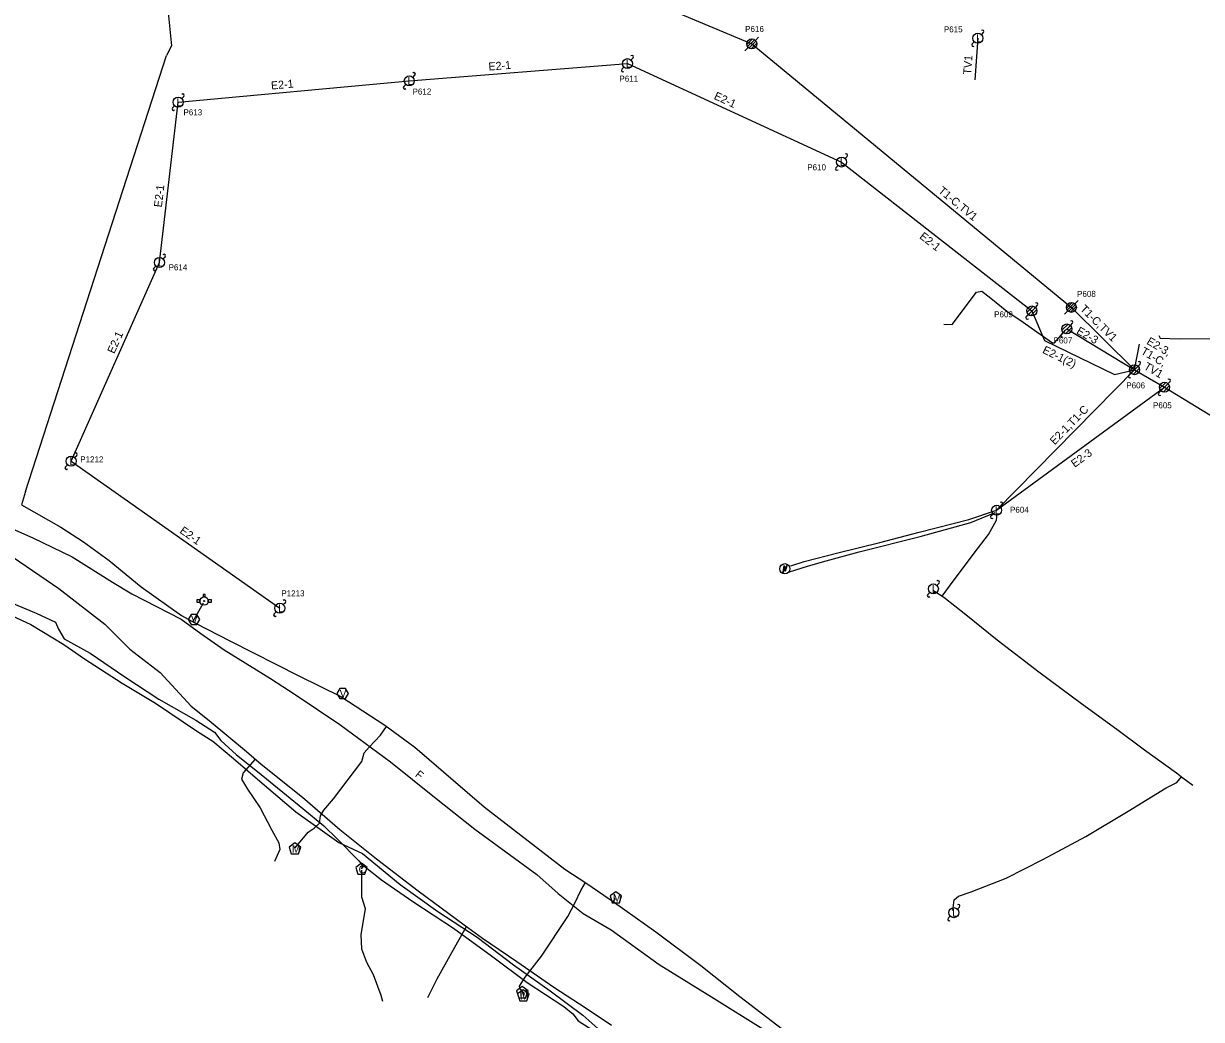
# Model space of a CAD drawing. Extents: x 1614474 to 1865144, y 1098877 to 1212550.
# Drawn here: x 1811697 to 1812286, y 1189385 to 1189883 of the extents above; entities that cross this region are included whole.
import ezdxf

# ---------------------------------------------------------------- set-up
doc = ezdxf.new("R2010")
doc.units = 0
for name, color, linetype in [('RD_EX_SU_Elec', 7, 'Continuous'), ('RD_EX_SU_Gas', 7, 'Continuous'), ('RD_EX_SU_H2O', 7, 'Continuous'), ('RD_EX_SU_Ovhd', 7, 'Continuous'), ('RD_EX_SU_Pole', 7, 'Continuous'), ('RD_EX_SU_Telecom', 7, 'Continuous'), ('RD_EX_SU_TX_Pole', 7, 'Continuous'), ('RD_EX_SU_TX_Telecom', 7, 'Continuous')]:
    doc.layers.add(name, color=color, linetype=linetype)

# ---------------------------------------------------------------- blocks, each defined once
blk = doc.blocks.new('SUE_PTP')
at = {"layer": 'RD_EX_SU_Pole'}
for p, q in [((-2.48, -0.33), (0.33, 2.48)), ((-2.1, -1.36), (1.36, 2.1)), ((-1.4, -2.08), (2.08, 1.4)), ((-0.38, -2.47), (2.47, 0.38)), ((1.77, 1.77), (3.42, 3.42)), ((-3.42, -3.42), (-1.77, -1.77)), ((1.52, -1.99), (1.99, -1.52))]:
    blk.add_line(p, q, dxfattribs=at)
blk.add_circle((0, 0), 2.5, dxfattribs=at)
blk = doc.blocks.new('SUE_PP')
at = {"layer": 'RD_EX_SU_Pole'}
for p, q in [((-2.41, -0.65), (0.65, 2.41)), ((-1.77, -1.77), (1.77, 1.77)), ((-0.65, -2.41), (2.41, 0.65)), ((1.77, 1.77), (2.83, 2.83)), ((-2.83, -2.83), (-1.77, -1.77))]:
    blk.add_line(p, q, dxfattribs=at)
blk.add_circle((0, 0), 2.5, dxfattribs=at)
for centre, start, end in [((2.3, 3.36), 315, 135), ((-2.3, -3.36), 135, 315)]:
    blk.add_arc(centre, 0.75, start, end, dxfattribs=at)
blk = doc.blocks.new('SUE_ETM')
at = {"layer": 'RD_EX_SU_Elec'}
blk.add_lwpolyline([(1.24, 2.04), (0.23, -1.41), (-0.27, 0.46), (-1.03, -2.36), (-0.34, 1.55), (0.22, -0.39)], close=True, dxfattribs=at)
blk.add_circle((0, 0), 2.55, dxfattribs=at)
blk = doc.blocks.new('SUE_TVP')
at = {"layer": 'RD_EX_SU_Telecom'}
blk.add_lwpolyline([(0, 3), (-2.85, 0.93), (-1.76, -2.43), (1.76, -2.43), (2.85, 0.93)], close=True, dxfattribs=at)
blk.add_text('C', height=4, dxfattribs=at).set_placement((-1.43, -2))
blk = doc.blocks.new('SUE_WM')
at = {"layer": 'RD_EX_SU_H2O'}
blk.add_lwpolyline([(0, 3.05), (-2.9, 0.94), (-1.79, -2.47), (1.79, -2.47), (2.9, 0.94)], close=True, dxfattribs=at)
blk.add_text('M', height=3.75, dxfattribs=at).set_placement((-1.43, -1.88))
blk = doc.blocks.new('SUE_WV')
at = {"layer": 'RD_EX_SU_H2O'}
blk.add_lwpolyline([(2.89, 0), (1.44, 2.5), (-1.44, 2.5), (-2.89, 0), (-1.44, -2.5), (1.44, -2.5)], close=True, dxfattribs=at)
blk.add_text('V', height=3.75, dxfattribs=at).set_placement((-1.43, -1.88))
blk = doc.blocks.new('SUE_WFH')
at = {"layer": 'RD_EX_SU_H2O'}
for p, q in [((-2.01, 0.6), (-3.65, 0.6)), ((-3.65, 0.6), (-3.65, -0.45)), ((-0.48, 3.38), (-0.48, 2.04)), ((0.57, 3.38), (-0.48, 3.38)), ((0.57, 2.02), (0.57, 3.38)), ((3.7, 0.6), (2.01, 0.6)), ((3.7, -0.45), (3.7, 0.6)), ((-3.65, -0.45), (-2.05, -0.45)), ((2.05, -0.45), (3.7, -0.45))]:
    blk.add_line(p, q, dxfattribs=at)
for radius in [2.1, 0.263]:
    blk.add_circle((0, 0), radius, dxfattribs=at)
for start, end in [(163.3387, 192.31502), (74.24552, 103.21276), (347.68498, 16.6613)]:
    blk.add_arc((0, 0), 2.1, start, end, dxfattribs=at)

msp = doc.modelspace()

# ---------------------------------------------------------------- linework, layer by layer
at = {"layer": 'RD_EX_SU_Elec'}
for points in [[(1812264.91, 1189727.31), (1812265.67, 1189726.04), (1812275.26, 1189725.72), (1812293.9, 1189725.79), (1812324.91, 1189726.47), (1812339.96, 1189726.45), (1812342, 1189727.19), (1812342.85, 1189729.51), (1812344.8, 1189746.63), (1812345.47, 1189768.56), (1812345.08, 1189790.52), (1812345.62, 1189813.9), (1812348.11, 1189828.63), (1812352.6, 1189838.52), (1812358.64, 1189853.73), (1812362.26, 1189854.61), (1812373.02, 1189852.36), (1812375.77, 1189853.01), (1812378.77, 1189855.94), (1812381.54, 1189860.45), (1812381.16, 1189864.31), (1812374.37, 1189871.78), (1812363.55, 1189880.36), (1812360.11, 1189887.91)], [(1812157.46, 1189732.89), (1812161.71, 1189732.8), (1812173.83, 1189748.94), (1812176.52, 1189749.55), (1812181.03, 1189746), (1812188.99, 1189739.47), (1812197.08, 1189733.89), (1812203.94, 1189729.08), (1812211.78, 1189723.64), (1812212.83, 1189723.64), (1812218.36, 1189729.98)], [(1812080.38, 1189609.13), (1812089.32, 1189611.99), (1812096.75, 1189614.2), (1812115.15, 1189619.16), (1812145.63, 1189626.78), (1812171.01, 1189633.82), (1812183.13, 1189638.8)], [(1812156.64, 1189596.96), (1812160.33, 1189602.07), (1812172.65, 1189618.48), (1812179.9, 1189627.9), (1812183.89, 1189634.91), (1812184.18, 1189638.37)], [(1812152.4, 1189599.89), (1812157.43, 1189596.42), (1812168.45, 1189587.78), (1812184.22, 1189575.11), (1812205.04, 1189559.15), (1812226.24, 1189543.39), (1812243.94, 1189530.5), (1812257.79, 1189520.12), (1812273.87, 1189508.71), (1812276.99, 1189506.25), (1812281.97, 1189502.57)], [(1812161.96, 1189439.78), (1812162.64, 1189445.19), (1812164.74, 1189447.02), (1812171.15, 1189449.17), (1812188.59, 1189456), (1812206.94, 1189465.3), (1812228.46, 1189476.83), (1812249.64, 1189489.48), (1812268.67, 1189501.17), (1812273.98, 1189503.93), (1812276.4, 1189506.71)]]:
    msp.add_lwpolyline(points, dxfattribs=at)
at = {"layer": 'RD_EX_SU_Gas'}
for points in [[(1811692.31, 1189616.25), (1811715.05, 1189600.87), (1811738.04, 1189583.07), (1811750.54, 1189570.51), (1811765.6, 1189558.89), (1811781.13, 1189542.05), (1811790.18, 1189534.92), (1811808.75, 1189519.41), (1811816.19, 1189513.02), (1811836.76, 1189496.52), (1811855.49, 1189480.41), (1811873.84, 1189465.7), (1811894.68, 1189449.62), (1811917.72, 1189432.69), (1811926.85, 1189425.98), (1811944.01, 1189414.44), (1811962.44, 1189401.55), (1811978.62, 1189391.11), (1811991.38, 1189382.56)], [(1811813.24, 1189515.56), (1811807.12, 1189508.75), (1811806.25, 1189505.55), (1811809.31, 1189500.44), (1811815.62, 1189491.11), (1811821.48, 1189479.96), (1811824.98, 1189473.64), (1811825.52, 1189470.37), (1811822.86, 1189464.34)], [(1811899.52, 1189396.32), (1811904.22, 1189405.75), (1811911.47, 1189418.83), (1811918.85, 1189431.86)]]:
    msp.add_lwpolyline(points, dxfattribs=at)
at = {"layer": 'RD_EX_SU_H2O'}
for p, q in [((1811698.38, 1189649.37), (1811768.81, 1189867.23)), ((1811781.92, 1189584.24), (1811787.36, 1189593.71)), ((1811992.21, 1189444.25), (1811993.36, 1189445.94))]:
    msp.add_line(p, q, dxfattribs=at)
for points in [[(1811749.01, 1190098.07), (1811749.34, 1190093.41), (1811749.33, 1190089.26), (1811749.37, 1190061.81), (1811749.88, 1190048.07), (1811750.21, 1190035.15), (1811751.18, 1190011.76), (1811751.52, 1190001.48), (1811754.59, 1189978.56), (1811759.5, 1189949.27), (1811762.38, 1189936.11), (1811766.27, 1189918.58), (1811768.53, 1189900.63), (1811771.29, 1189872.1), (1811768.81, 1189867.23)], [(1811698.38, 1189649.37), (1811696.33, 1189642.69), (1811716.07, 1189631.57), (1811727.27, 1189624.19), (1811740.19, 1189614.8), (1811756.23, 1189601.68), (1811776.38, 1189587.41), (1811783.03, 1189583.6), (1811800.81, 1189574.54), (1811834.94, 1189557.09), (1811855.92, 1189546.76), (1811878.04, 1189532.45), (1811892.99, 1189521.5), (1811927.74, 1189491.64), (1811968.06, 1189460.58), (1811978.97, 1189453.42), (1811992.89, 1189443.78), (1812013.48, 1189429.12), (1812036.07, 1189412.42), (1812055.57, 1189396.84), (1812100.91, 1189362.09), (1812129.54, 1189341.4), (1812152.59, 1189324.09), (1812186.12, 1189296.74)], [(1811833.17, 1189471.16), (1811839.64, 1189479.07), (1811842.69, 1189480.95), (1811845.36, 1189483.48), (1811845.85, 1189487.16), (1811847.57, 1189490.08), (1811852.4, 1189495.67), (1811866.54, 1189514.32), (1811867.72, 1189518.7), (1811870.1, 1189521.47), (1811875.88, 1189527.52), (1811878.77, 1189531.91)], [(1811947.49, 1189397.66), (1811947.36, 1189398.85), (1811945.67, 1189400.6), (1811945.28, 1189402.05), (1811948.11, 1189406.49), (1811956.4, 1189417.11), (1811969.45, 1189436.94), (1811973.24, 1189443.82), (1811975.95, 1189449.81), (1811978.25, 1189453.9)]]:
    msp.add_lwpolyline(points, dxfattribs=at)
at = {"layer": 'RD_EX_SU_Ovhd'}
for p, q in [((1811952.33, 1189919.06), (1812061.47, 1189873.07)), ((1812174.5, 1189875.89), (1812172.94, 1189855.19)), ((1812061.47, 1189873.07), (1812221.25, 1189741.38)), ((1811890.24, 1189854.59), (1811999.3, 1189863.2)), ((1811999.3, 1189863.2), (1812106.35, 1189814.02)), ((1811774.66, 1189843.94), (1811890.24, 1189854.59)), ((1811765.29, 1189763.8), (1811774.66, 1189843.94)), ((1812106.35, 1189814.02), (1812201.52, 1189739.58)), ((1811721.11, 1189664.49), (1811765.29, 1189763.8)), ((1812221.25, 1189741.38), (1812252.81, 1189710.2)), ((1812218.97, 1189730.56), (1812252.81, 1189710.2)), ((1812252.81, 1189710.2), (1812255.27, 1189723.05)), ((1812183.9, 1189639.95), (1812252.81, 1189710.2)), ((1812252.81, 1189710.2), (1812267.77, 1189701.43)), ((1812183.9, 1189639.95), (1812267.77, 1189701.43)), ((1812267.77, 1189701.43), (1812440.67, 1189595.6)), ((1811721.11, 1189664.49), (1811825.45, 1189590.98))]:
    msp.add_line(p, q, dxfattribs=at)
msp.add_lwpolyline([(1812201.52, 1189739.58), (1812207.78, 1189724.76), (1812242.82, 1189707.8), (1812252.81, 1189710.2)], dxfattribs=at)
at = {"layer": 'RD_EX_SU_Pole'}
for p, q in [((1812171.67, 1189873.06), (1812172.73, 1189874.12)), ((1812176.26, 1189877.66), (1812177.32, 1189878.72)), ((1812001.07, 1189864.96), (1812002.13, 1189866.03)), ((1811892.01, 1189856.36), (1811893.07, 1189857.42)), ((1811996.47, 1189860.37), (1811997.53, 1189861.43)), ((1811887.41, 1189851.77), (1811888.47, 1189852.83)), ((1811776.43, 1189845.7), (1811777.49, 1189846.76)), ((1811771.84, 1189841.11), (1811772.9, 1189842.17)), ((1812108.12, 1189815.79), (1812109.18, 1189816.85)), ((1812103.52, 1189811.19), (1812104.58, 1189812.25)), ((1811762.46, 1189760.97), (1811763.52, 1189762.03)), ((1811767.06, 1189765.57), (1811768.12, 1189766.63)), ((1812223.02, 1189743.15), (1812224.67, 1189744.8)), ((1812199.11, 1189738.93), (1812202.17, 1189741.99)), ((1812199.75, 1189737.81), (1812203.29, 1189741.34)), ((1812200.88, 1189737.16), (1812203.94, 1189740.22)), ((1812203.29, 1189741.34), (1812204.35, 1189742.41)), ((1812217.82, 1189737.96), (1812219.48, 1189739.61)), ((1812218.77, 1189741.05), (1812221.58, 1189743.86)), ((1812219.15, 1189740.02), (1812222.61, 1189743.48)), ((1812219.85, 1189739.3), (1812223.32, 1189742.78)), ((1812220.87, 1189738.91), (1812223.72, 1189741.76)), ((1812222.77, 1189739.39), (1812223.23, 1189739.86)), ((1812198.69, 1189736.75), (1812199.75, 1189737.81)), ((1812250.39, 1189709.55), (1812253.46, 1189712.61)), ((1812251.04, 1189708.43), (1812254.58, 1189711.97)), ((1812252.16, 1189707.79), (1812255.22, 1189710.85)), ((1812254.58, 1189711.97), (1812255.64, 1189713.03)), ((1812249.98, 1189707.37), (1812251.04, 1189708.43)), ((1812265.36, 1189700.78), (1812268.42, 1189703.84)), ((1812266, 1189699.66), (1812269.54, 1189703.19)), ((1812269.54, 1189703.19), (1812270.6, 1189704.25)), ((1812264.94, 1189698.6), (1812266, 1189699.66)), ((1812267.13, 1189699.01), (1812270.19, 1189702.07)), ((1811718.28, 1189661.66), (1811719.34, 1189662.72)), ((1811722.87, 1189666.26), (1811723.94, 1189667.32)), ((1812181.07, 1189637.12), (1812182.13, 1189638.18)), ((1812185.66, 1189641.71), (1812186.72, 1189642.78)), ((1812154.03, 1189602.41), (1812155.09, 1189603.47)), ((1812149.44, 1189597.82), (1812150.5, 1189598.88)), ((1811827.21, 1189592.75), (1811828.27, 1189593.81)), ((1811822.62, 1189588.16), (1811823.68, 1189589.22)), ((1812164.26, 1189440.55), (1812165.32, 1189441.61)), ((1812159.66, 1189435.95), (1812160.72, 1189437.01))]:
    msp.add_line(p, q, dxfattribs=at)
for centre in [(1812174.5, 1189875.89), (1811999.3, 1189863.2), (1811890.24, 1189854.59), (1811774.66, 1189843.94), (1812106.35, 1189814.02), (1811765.29, 1189763.8), (1812201.52, 1189739.58), (1812221.25, 1189741.38), (1812252.81, 1189710.2), (1812267.77, 1189701.43), (1811721.11, 1189664.49), (1812183.9, 1189639.95), (1812152.26, 1189600.64), (1811825.45, 1189590.98), (1812162.49, 1189438.78)]:
    msp.add_circle(centre, 2.5, dxfattribs=at)
for centre, start, end in [((1812176.79, 1189879.25), 315, 135), ((1812172.2, 1189872.53), 135, 315), ((1812001.6, 1189866.56), 315, 135), ((1811892.54, 1189857.95), 315, 135), ((1811997, 1189859.84), 135, 315), ((1811887.94, 1189851.24), 135, 315), ((1811776.96, 1189847.3), 315, 135), ((1811772.37, 1189840.58), 135, 315), ((1812108.65, 1189817.38), 315, 135), ((1812104.05, 1189810.66), 135, 315), ((1811767.59, 1189767.16), 315, 135), ((1811762.99, 1189760.44), 135, 315), ((1812203.82, 1189742.94), 315, 135), ((1812199.22, 1189736.22), 135, 315), ((1812255.11, 1189713.56), 315, 135), ((1812250.51, 1189706.84), 135, 315), ((1812270.07, 1189704.78), 315, 135), ((1812265.47, 1189698.07), 135, 315), ((1811723.41, 1189667.85), 315, 135), ((1811718.81, 1189661.13), 135, 315), ((1812186.19, 1189643.31), 315, 135), ((1812181.6, 1189636.59), 135, 315), ((1812154.56, 1189604), 315, 135), ((1812149.97, 1189597.29), 135, 315), ((1811827.74, 1189594.34), 315, 135), ((1811823.15, 1189587.63), 135, 315), ((1812164.79, 1189442.14), 315, 135), ((1812160.19, 1189435.42), 135, 315)]:
    msp.add_arc(centre, 0.75, start, end, dxfattribs=at)
at = {"layer": 'RD_EX_SU_Telecom'}
for points in [[(1812080.94, 1189612.23), (1812087.64, 1189614.38), (1812104.55, 1189618.61), (1812125.45, 1189623.75), (1812145.2, 1189628.92), (1812170.06, 1189635.3), (1812183.37, 1189639.83)], [(1811678.57, 1189636.54), (1811702.02, 1189626.09), (1811721.66, 1189616.6), (1811741.84, 1189603.98), (1811751.48, 1189598.22), (1811776.15, 1189585.54), (1811786, 1189578.31), (1811797.6, 1189570.11), (1811820.85, 1189555.77), (1811833.2, 1189547.84), (1811855.44, 1189532.83), (1811880.8, 1189514.22), (1811902.8, 1189496.6), (1811923.07, 1189480.55), (1811953.95, 1189457.83), (1811964.7, 1189448.3), (1811977.24, 1189438.31), (1811991.12, 1189430.27), (1812015.08, 1189412.93), (1812041.31, 1189396.63), (1812067.45, 1189380.42)], [(1811576.48, 1189627.18), (1811591.3, 1189624), (1811619.72, 1189617.72), (1811647.4, 1189609.75), (1811676.84, 1189599.71), (1811703.64, 1189588.56), (1811713.39, 1189584.03), (1811714.86, 1189580.51), (1811717.73, 1189575.64), (1811730.58, 1189568.58), (1811747.95, 1189556.7), (1811765.04, 1189545.45), (1811783.53, 1189535.07), (1811792.79, 1189528.95), (1811796.05, 1189524.9), (1811803.9, 1189517.67), (1811814.32, 1189509.32), (1811837.05, 1189490.91), (1811847.41, 1189482.26), (1811854.37, 1189475.52), (1811865.03, 1189464.68), (1811866.6, 1189462.7), (1811866.26, 1189460.76)], [(1811674.94, 1189594.9), (1811701.01, 1189582.82), (1811717.47, 1189572.89), (1811727.78, 1189565.75), (1811746.64, 1189553.45), (1811763.29, 1189543.56), (1811784.27, 1189529.35), (1811792, 1189524.45), (1811802.3, 1189515.8), (1811815.51, 1189504.47), (1811833.48, 1189489.14), (1811846.85, 1189479.64), (1811855.03, 1189473.8), (1811866.89, 1189468.42), (1811885.7, 1189452.8), (1811904.46, 1189439.39), (1811924.08, 1189426.58), (1811942.4, 1189412.71), (1811960.58, 1189399.63), (1811977.05, 1189387.58), (1811986.06, 1189379.62)], [(1811866.54, 1189460.89), (1811867.57, 1189462.27), (1811876.31, 1189455.22), (1811892.02, 1189444.39), (1811912.27, 1189431.03), (1811931.3, 1189417.22), (1811949.14, 1189403.92), (1811967.5, 1189391.86), (1811971.97, 1189388.13), (1811974.74, 1189384.76), (1811984.65, 1189378.44), (1811998.06, 1189370.34), (1812018.19, 1189357.33), (1812029.4, 1189350.87), (1812052.3, 1189334.6), (1812058.9, 1189329.54), (1812059.36, 1189328.63), (1812058.74, 1189327.92)], [(1811866.37, 1189459.99), (1811866.38, 1189446.69), (1811868.1, 1189440.94), (1811865.95, 1189427.73), (1811866.32, 1189420.78), (1811868.9, 1189414.11), (1811872.23, 1189407.94), (1811875.98, 1189397.5), (1811876.88, 1189394.53)]]:
    msp.add_lwpolyline(points, dxfattribs=at)

# ---------------------------------------------------------------- block references
at = {"layer": 'RD_EX_SU_Elec'}
msp.add_blockref('SUE_ETM', (1812077.98, 1189610.7), dxfattribs=at)
at = {"layer": 'RD_EX_SU_H2O'}
for name, p in [('SUE_WFH', (1811787.6, 1189594.53)), ('SUE_WV', (1811782.52, 1189585.41)), ('SUE_WV', (1811856.86, 1189548.29)), ('SUE_WM', (1811833.01, 1189470.65)), ('SUE_WM', (1811993.48, 1189446.19)), ('SUE_WM', (1811946.72, 1189398.75)), ('SUE_WM', (1811947.23, 1189397.21))]:
    msp.add_blockref(name, p, dxfattribs=at)
at = {"layer": 'RD_EX_SU_Pole'}
msp.add_blockref('SUE_PP', (1812218.97, 1189730.56), dxfattribs=at)
at = {"layer": 'RD_EX_SU_Telecom'}
for name, p in [('SUE_PTP', (1812061.47, 1189873.07)), ('SUE_TVP', (1811866.3, 1189460.48))]:
    msp.add_blockref(name, p, dxfattribs=at)

# ---------------------------------------------------------------- texts
at = {"layer": 'RD_EX_SU_Ovhd'}
for s, rotation, p in [('E2-1', 4.51009, (1811929.97, 1189859.73)), ('TV1', 85.70236, (1812171.11, 1189857.57)), ('E2-1', 5.26874, (1811821.27, 1189850.24)), ('E2-1', 335.32659, (1812042.21, 1189845.68)), ('E2-1', 83.32741, (1811766.48, 1189791.23)), ('T1-C,TV1', 320.50578, (1812154.39, 1189799.07)), ('E2-1', 321.96851, (1812144.99, 1189776.18)), ('T1-C,TV1', 315.34892, (1812225.28, 1189740.21)), ('E2-1', 66.01654, (1811742.69, 1189717.92)), ('E2-3', 330.19574, (1812223.43, 1189728.46)), ('E2-3,', 329.61551, (1812258.56, 1189723.31)), ('E2-1(2)', 334.17273, (1812206.46, 1189718.74)), ('T1-C,', 329.61551, (1812255.64, 1189718.33)), ('TV1', 329.61551, (1812257.14, 1189710.76)), ('E2-1,T1-C', 45.55166, (1812212.89, 1189672.36)), ('E2-3', 36.24049, (1812222.93, 1189661.12)), ('E2-1', 324.83551, (1811775.09, 1189628.91))]:
    msp.add_text(s, height=4, rotation=rotation, dxfattribs=at).set_placement(p)
at = {"layer": 'RD_EX_SU_Pole'}
for p in [(1812173.63, 1189873.89), (1811998.44, 1189861.2), (1811889.38, 1189852.59), (1811773.8, 1189841.94), (1812105.49, 1189812.02), (1811764.43, 1189761.8), (1811720.24, 1189662.49), (1812183.03, 1189637.95), (1812151.4, 1189598.64), (1811824.58, 1189588.98), (1812161.63, 1189436.78)]:
    msp.add_text('L', height=4, dxfattribs=at).set_placement(p)
at = {"layer": 'RD_EX_SU_TX_Pole'}
for s, p in [('P616', (1812058.15, 1189879.05)), ('P615', (1812157.5, 1189878.86)), ('P611', (1811995.27, 1189854.2)), ('P612', (1811891.85, 1189847.76)), ('P613', (1811777.3, 1189837.38)), ('P610', (1812089.21, 1189809.89)), ('P614', (1811769.88, 1189759.91)), ('P608', (1812224.11, 1189746.62)), ('P609', (1812182.64, 1189736.39)), ('P607', (1812212.34, 1189723.33)), ('P606', (1812248.72, 1189700.85)), ('P605', (1812262.08, 1189690.92)), ('P1212', (1811725.69, 1189663.89)), ('P604', (1812190.58, 1189638.68)), ('P1213', (1811826.23, 1189596.93))]:
    msp.add_text(s, height=3, dxfattribs=at).set_placement(p)
at = {"layer": 'RD_EX_SU_TX_Telecom'}
msp.add_text('F', height=4, rotation=321.3273, dxfattribs=at).set_placement((1811892.8, 1189507.17))

doc.saveas('drawing.dxf')
